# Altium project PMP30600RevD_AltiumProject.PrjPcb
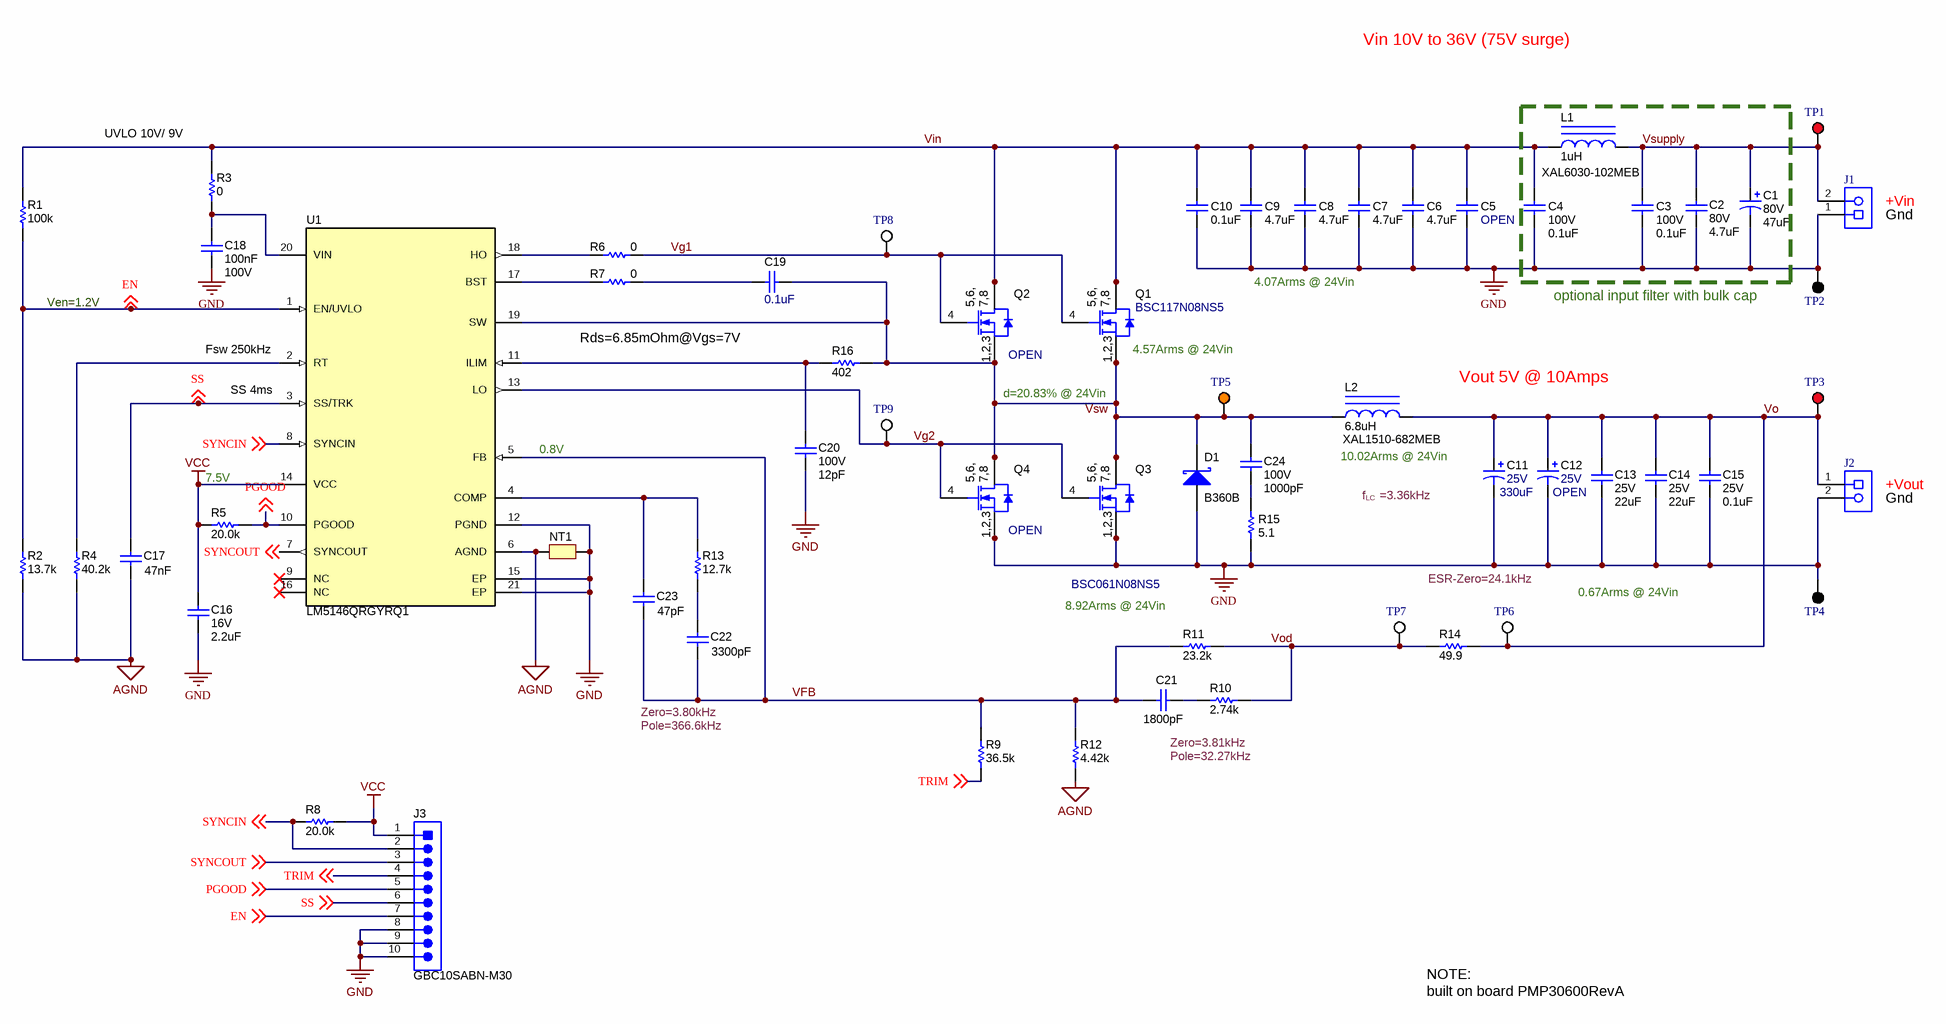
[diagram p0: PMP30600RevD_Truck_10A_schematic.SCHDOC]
TID: N/A; TechSupport: http://www.ti.com/support; SCH_Rev: D; PRJ_Title: Automotive Pre Regulator 10A (Truck); PRJ_Number: PMP30600-TL; PRJ_Engineer: Nobukazu Tsukiji; PRJ_Customer: Public Release; PCB_Rev: A; PCB_Layout: Who did the Layout?
1 sheet, 61 parts. Net scope: global (net labels, ports and power ports of the same name join across sheets).
Board file: PMP30600RevA_board.PcbDoc

## Sheet PMP30600RevD_Truck_10A_schematic.SCHDOC
size 431 x 279 mm; Date: Not shown in title block; ApprovedBy: Not shown in title block; CheckedBy: Not shown in title block; Author: Not shown in title block; CompanyName: Not shown in title block; Engineer: Not shown in title block; Organization: Not shown in title block; Address1: Not shown in title block; Address2: Not shown in title block; Address3: Not shown in title block; Address4: Not shown in title block; DocumentNumber: 1; Revision: Use project parameter SCH_Rev; SheetNumber: 1; SheetTotal: 1; PageSetup: Record=PageOptions¦CenterHorizontal=True¦CenterVertical=True¦PrintScale=0.70¦XCorrection=1.00¦YCorrection=1.00¦PrintKind=0¦BorderSize=5000000¦LeftOffset=0¦BottomOffset=0¦Orientation=2¦PaperLength=1000¦PaperWidth=1000¦Scale=100¦PaperSource=15¦PrintQuality=600¦MediaType=1¦DitherType=10¦PaperKind=A4¦PrintScaleMode=1

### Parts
C1  VDC_V: 80V  ValueDisplayed: 47uF  [SM_RADIAL_6.3AMM]  (hidden comment: EEHZC1K470P)
C2  VDC_V: 80V  ValueDisplayed: 4.7uF  [1210_270]  (hidden comment: GRM32ER71K475KE14L)
C3  VDC_V: 100V  ValueDisplayed: 0.1uF  [0603]  (hidden comment: GRM188R72A104KA35J)
C4  VDC_V: 100V  ValueDisplayed: 0.1uF  [0603]  (hidden comment: GRM188R72A104KA35J)
C5  ValueDisplayed: OPEN  [1210_270]  (hidden comment: Capacitor)
C6  ValueDisplayed: 4.7uF  [1210_270]  (hidden comment: GRM32ER71K475KE14L)
C7  ValueDisplayed: 4.7uF  [1210_270]  (hidden comment: GRM32ER71K475KE14L)
C8  ValueDisplayed: 4.7uF  [1210_270]  (hidden comment: GRM32ER71K475KE14L)
C9  ValueDisplayed: 4.7uF  [1210_270]  (hidden comment: GRM32ER71K475KE14L)
C10  ValueDisplayed: 0.1uF  [0603]  (hidden comment: GRM188R72A104KA35J)
C11  VDC_V: 25V  ValueDisplayed: 330uF  [SM_RADIAL_10BMM]  (hidden comment: EEHZC1E331P)
C12  VDC_V: 25V  ValueDisplayed: OPEN  [SM_RADIAL_10BMM]  (hidden comment: EEHZC1E331P)
C13  VDC_V: 25V  ValueDisplayed: 22uF  [1210_270]  (hidden comment: GRM32ER71E226KE15L)
C14  VDC_V: 25V  ValueDisplayed: 22uF  [1210_270]  (hidden comment: GRM32ER71E226KE15L)
C15  VDC_V: 25V  ValueDisplayed: 0.1uF  [0603]  (hidden comment: GRM188R71E104KA01D)
C16  VDC_V: 16V  ValueDisplayed: 2.2uF  [0805_HV]  (hidden comment: GRM21BR71C225KA12L)
C17  ValueDisplayed: 47nF  [0603]  (hidden comment: GRM188R71E473KA01D)
C18  Cap_F: 100nF  VDC_V: 100V  [0603]  (hidden comment: GRM188R72A104KA35D)
C19  ValueDisplayed: 0.1uF  [0603]  (hidden comment: Capacitor)
C20  VDC_V: 100V  ValueDisplayed: 12pF  [0603]  (hidden comment: GRM1885C2A120JA01D)
C21  ValueDisplayed: 1800pF  [0603]  (hidden comment: GRM1885C1H182JA01D)
C22  ValueDisplayed: 3300pF  [0603]  (hidden comment: GRM1885C1H332JA01D)
C23  ValueDisplayed: 47pF  [0603]  (hidden comment: GRM1885C1H470JA01D)
C24  VDC_V: 100V  ValueDisplayed: 1000pF  [0805_HV]  (hidden comment: C0805C102K1RACTU)
D1  PartNumberDisplayed: B360B  [SMB]  (hidden comment: B360B-13-F)
J1  691214110002  [Wurth_691214110002]  (value not drawn)
J2  691236510002  [Wurth_691236510002]  (value not drawn)
J3  GBC10SABN-M30  [Sullins_GBC10SABN-M30]
L1  XAL6030-102MEB  ValueDisplayed: 1uH  [XAL6030]
L2  ValueDisplayed: 6.8uH  [XAL1510]  (hidden comment: XAL1510-682MEB)
NT1  Net-Tie  [Net-Tie_10milWide_30milLong]  (value not drawn)  (net tie, no BOM)
Q1  BSC117N08NS5  [PG-TDSON-8]
Q2  OPEN  [PG-TDSON-8]
Q3  BSC061N08NS5  [PG-TDSON-8]
Q4  OPEN  [PG-TDSON-8]
R1  ValueDisplayed: 100k  [0603]  (hidden comment: CRCW0603100KFKEA)
R2  ValueDisplayed: 13.7k  [0603]  (hidden comment: CRCW060313K7FKEA)
R3  ValueDisplayed: 0  [0603]  (hidden comment: RMCF0603ZT0R00)
R4  ValueDisplayed: 40.2k  [0603]  (hidden comment: CRCW060340K2FKEA)
R5  ValueDisplayed: 20.0k  [0603]  (hidden comment: CRCW060320K0FKEA)
R6  ValueDisplayed: 0  [0603]  (hidden comment: RMCF0603ZT0R00)
R7  ValueDisplayed: 0  [0603]  (hidden comment: RMCF0603ZT0R00)
R8  ValueDisplayed: 20.0k  [0603]  (hidden comment: CRCW060320K0FKEA)
R9  ValueDisplayed: 36.5k  [0603]  (hidden comment: RC0603FR-0736K5L)
R10  ValueDisplayed: 2.74k  [0603]  (hidden comment: CRCW06032K74FKEA)
R11  ValueDisplayed: 23.2k  [0603]  (hidden comment: CRCW060323K2FKEA)
R12  ValueDisplayed: 4.42k  [0603]  (hidden comment: CRCW06034K42FKEA)
R13  ValueDisplayed: 12.7k  [0603]  (hidden comment: CRCW060312K7FKEA)
R14  ValueDisplayed: 49.9  [0603]  (hidden comment: CRCW060349R9FKEA)
R15  ValueDisplayed: 5.1  [1210]  (hidden comment: RC1210JR-075R1L)
R16  ValueDisplayed: 402  [0603]  (hidden comment: CRCW0603402RFKEA)
TP1  5000  [Keystone5000]  (value not drawn)
TP2  5001  [Keystone5001]  (value not drawn)
TP3  5000  [Keystone5000]  (value not drawn)
TP4  5001  [Keystone5001]  (value not drawn)
TP5  5003  [Keystone5003]  (value not drawn)
TP6  5002  [Keystone5002]  (value not drawn)
TP7  5002  [Keystone5002]  (value not drawn)
TP8  5002  [Keystone5002]  (value not drawn)
TP9  5002  [Keystone5002]  (value not drawn)
U1  LM5146QRGYRQ1  [RGY0020B]

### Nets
AGND: C17.2 NT1.1 R2.1 R4.1 R12.1 U1.6(AGND)
GND: C1.2(-) C2.2 C3.2 C4.2 C5.2 C6.2 C7.2 C8.2 C9.2 C10.2 C11.2(-) C12.2(-) C13.2 C14.2 C15.2 C16.2 C18.2 C20.2 D1.2(A) J1.1 J2.2 J3.8 J3.9 J3.10 NT1.2 Q3.1(S) Q3.2(S) Q3.3(S) Q4.1(S) Q4.2(S) Q4.3(S) R15.1 TP2.1 TP4.1 U1.12(PGND) U1.15(EP) U1.21(EP)
VCC: C16.1 J3.1 R5.1 R8.2 U1.14(VCC)
EN: J3.7 R1.1 R2.2 U1.1(EN/UVLO) ; off-sheet EN
PGOOD: J3.5 R5.2 U1.10(PGOOD) ; off-sheet PGOOD
SS: C17.1 J3.6 U1.3(SS/TRK) ; off-sheet SS
SYNCIN: J3.2 R8.1 U1.8(SYNCIN) ; off-sheet SYNCIN
SYNCOUT: J3.3 U1.7(SYNCOUT) ; off-sheet SYNCOUT
TRIM: J3.4 R9.1 ; off-sheet TRIM
VFB: C21.2 C22.1 C23.1 R9.2 R11.1 R12.2 U1.5(FB)
Vg1: Q1.4(G) Q2.4(G) R6.2 TP8.1
Vg2: Q3.4(G) Q4.4(G) TP9.1 U1.13(LO)
Vin: C4.1 C5.1 C6.1 C7.1 C8.1 C9.1 C10.1 L1.1 Q1.5(D) Q1.6(D) Q1.7(D) Q1.8(D) Q1.9(D) Q2.5(D) Q2.6(D) Q2.7(D) Q2.8(D) Q2.9(D) R1.2 R3.2
Vo: C11.1(+) C12.1(+) C13.1 C14.1 C15.1 J2.1 L2.2 R14.2 TP3.1 TP6.1
Vod: R10.2 R11.2 R14.1 TP7.1
Vsupply: C1.1(+) C2.1 C3.1 J1.2 L1.2 TP1.1
NetC18_1: C18.1 R3.1 U1.20(VIN)
NetC19_1: C19.1 R7.2
NetC19_2: C19.2 C24.1 D1.1(K) L2.1 Q1.1(S) Q1.2(S) Q1.3(S) Q2.1(S) Q2.2(S) Q2.3(S) Q3.5(D) Q3.6(D) Q3.7(D) Q3.8(D) Q3.9(D) Q4.5(D) Q4.6(D) Q4.7(D) Q4.8(D) Q4.9(D) R16.2 TP5.1 U1.19(SW)
NetC20_1: C20.1 R16.1 U1.11(ILIM)
NetC21_1: C21.1 R10.1
NetC22_2: C22.2 R13.2
NetC23_2: C23.2 R13.1 U1.4(COMP)
NetC24_2: C24.2 R15.2
NetR4_2: R4.2 U1.2(RT)
NetR6_1: R6.1 U1.18(HO)
NetR7_1: R7.1 U1.17(BST)

Not connected (* = marked no-connect by the designer): U1 9(NC)* 16(NC)*

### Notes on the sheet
- Vin 10V to 36V (75V surge)
- (near R3) UVLO 10V/ 9V
- (near J1) +Vin
- (near J1) Gnd
- 4.07Arms @ 24Vin
- Ven=1.2V
- (near U1) Fsw 250kHz
- Rds=6.85mOhm@Vgs=7V
  ILIM=13A
- (near Q1) 4.57Arms @ 24Vin
- (near TP2) optional input filter with bulk cap
- (near U1) SS 4ms
- d=20.83% @ 24Vin
- Vout 5V @ 10Amps
- (near R5) 7.5V
- (near U1) 0.8V
- 10.02Arms @ 24Vin
- (near J2) +Vout
- LC
- f    =3.36kHz
- (near J2) Gnd
- (near R11) 8.92Arms @ 24Vin
- ESR-Zero=24.1kHz
- 0.67Arms @ 24Vin
- Zero=3.80kHz
- Pole=366.6kHz
- Zero=3.81kHz
- Pole=32.27kHz
- built on board PMP30600RevA
- NOTE:
- Labels drawn without touching a wire or pin: Vsw

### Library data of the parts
C1 = CMP-0012607-3: CAP, Polymer Hybrid, 47 uF, 35 V, +/- 20%, 60 ohm, 6.3x5.8 SMD; Manufacturer: Panasonic; PartNumber: EEHZC1V470P; TaMin_C: -55°C; ESR_ohm: 60; Polarized: Y; SizeAreaWB_mm2: 79.98; Value1: 60 ohm; Value: 47uF; TaMax_C: 125°C; SizeZ_mm: 6; SizeX_mm: 7.3; SizeY_mm: 6.6; Value2: 35V; SizeArea_mm2: 48.18; CompType: Capacitor; Cap_F: 47µF; IRMS_A: 900mA; AEC Category: Q200
C2 = CMP-0009230-2: CAP, CERM, 4.7 uF, 80 V, +/- 10%, X7R, 1210; Manufacturer: MuRata; TaMin_C: -55°C; Polarized: N; SizeAreaWB_mm2: 14.7; Value1: Unknown; U/M: EA; Value: 4.7uF; TaMax_C: 125°C; SizeZ_mm: 2.7; SizeX_mm: 3.2; SizeY_mm: 2.5; Cap_Case: 1210; SizeArea_mm2: 8; Cap_F: 4.7µF; AEC Category: Q200
C3 C4 = CMP-0007470-5: CAP, CERM, 0.1 uF, 100 V, +/- 10%, X7R, 0603; Manufacturer: MuRata; TaMin_C: -55°C; Polarized: N; SizeAreaWB_mm2: 4.68; Value1: Unknown; U/M: EA; Value: 0.1uF; TaMax_C: 125°C; SizeZ_mm: 1; SizeX_mm: 1.6; SizeY_mm: 0.8; SizeArea_mm2: 1.28; Cap_F: 100nF; AEC Category: Q200
C5 = CMP-0009226-3: CAP, CERM, 10 uF, 50 V, +/- 10%, X7R, 1210; PartNumber: GRM32ER71H106KA12L; Manufacturer: MuRata; Polarized: N; Value: 10uF; U/M: EA; Cap_F: 10µF; Value1: Unknown; VDC_V: 50V; TaMin_C: -55°C; TaMax_C: 125°C; Cap_Case: 1210; SizeArea_mm2: 8; SizeAreaWB_mm2: 14.7; SizeX_mm: 3.2; SizeY_mm: 2.5; SizeZ_mm: 2.7; AEC Category: Q200
C6-C9 = CMP-0009230-2: CAP, CERM, 4.7 uF, 80 V, +/- 10%, X7R, 1210; Manufacturer: MuRata; TaMin_C: -55°C; Polarized: N; SizeAreaWB_mm2: 14.7; Value1: Unknown; U/M: EA; Value: 4.7uF; TaMax_C: 125°C; SizeZ_mm: 2.7; SizeX_mm: 3.2; SizeY_mm: 2.5; Cap_Case: 1210; Value2: 80V; SizeArea_mm2: 8; Cap_F: 4.7µF; AEC Category: Q200
C10 = CMP-0007470-5: CAP, CERM, 0.1 uF, 100 V, +/- 10%, X7R, 0603; Manufacturer: MuRata; TaMin_C: -55°C; Polarized: N; SizeAreaWB_mm2: 4.68; Value1: Unknown; U/M: EA; Value: 0.1uF; TaMax_C: 125°C; SizeZ_mm: 1; SizeX_mm: 1.6; SizeY_mm: 0.8; Value2: 100V; SizeArea_mm2: 1.28; Cap_F: 100nF; AEC Category: Q200
C11 C12 = CMP-0012593-1: CAP, Polymer Hybrid, 330 uF, 25 V, +/- 20%, 20 ohm, 10x10 SMD; Manufacturer: Panasonic; TaMin_C: -55°C; ESR_ohm: 20; Polarized: Y; SizeAreaWB_mm2: 159.9; Value1: 20 ohm; U/M: EA; Value: 330uF; TaMax_C: 125°C; SizeZ_mm: 10.2; SizeX_mm: 11; SizeY_mm: 10.3; SizeArea_mm2: 113.3; CompType: Capacitor; Cap_F: 330µF; IRMS_A: 2A; AEC Category: Q200
C13 C14 = CMP-0009224-2: CAP, CERM, 22 uF, 25 V, +/- 10%, X7R, 1210; Manufacturer: MuRata; TaMin_C: -55°C; Polarized: N; SizeAreaWB_mm2: 14.7; Value1: Unknown; U/M: EA; Value: 22uF; TaMax_C: 125°C; SizeZ_mm: 2.7; SizeX_mm: 3.2; SizeY_mm: 2.5; Cap_Case: 1210; SizeArea_mm2: 8; Cap_F: 22µF; AEC Category: Q200
C15 = CMP-0007404-4: CAP, CERM, 0.1 uF, 25 V, +/- 10%, X7R, 0603; Manufacturer: MuRata; TaMin_C: -55°C; Polarized: N; SizeAreaWB_mm2: 4.68; Value1: Unknown; U/M: EA; Value: 0.1uF; TaMax_C: 125°C; SizeZ_mm: 1; SizeX_mm: 1.6; SizeY_mm: 0.8; SizeArea_mm2: 1.28; Cap_F: 100nF; AEC Category: Q200
C16 = CMP-0008329-2: CAP, CERM, 2.2 uF, 16 V, +/- 10%, X7R, 0805; Manufacturer: MuRata; TaMin_C: -55°C; ESR_ohm: 4m; Polarized: N; SizeAreaWB_mm2: 6.75; Value1: 0.004 ohm; U/M: EA; Value: 2.2uF; TaMax_C: 125°C; SizeZ_mm: 1.45; SizeX_mm: 2; SizeY_mm: 1.25; Cap_Case: 0805; SizeArea_mm2: 2.5; Cap_F: 2.2µF; AEC Category: Q200
C17 = CMP-0007423-4: CAP, CERM, 0.047 uF, 25 V, +/- 10%, X7R, 0603; Manufacturer: MuRata; TaMin_C: -55°C; Polarized: N; SizeAreaWB_mm2: 4.68; Value1: Unknown; U/M: EA; TaMax_C: 125°C; SizeZ_mm: 1; SizeX_mm: 1.6; SizeY_mm: 0.8; Value2: 25V; SizeArea_mm2: 1.28; AEC Category: Q200
C18 = CMP-0007469-4: CAP, CERM, 0.1 uF, 100 V, +/- 10%, X7R, 0603; Manufacturer: MuRata; TaMin_C: -55°C; Polarized: N; SizeAreaWB_mm2: 4.68; Value1: Unknown; U/M: EA; Value: 0.1uF; TaMax_C: 125°C; SizeZ_mm: 1; SizeX_mm: 1.6; SizeY_mm: 0.8; SizeArea_mm2: 1.28; AEC Category: Q200
C19 = CMP-0007434-4: CAP, CERM, 0.1 uF, 50 V, +/- 10%, X7R, 0603; PartNumber: GRM188R71H104KA93D; Manufacturer: MuRata; Polarized: N; Value: 0.1uF; U/M: EA; Cap_F: 100nF; Value1: Unknown; VDC_V: 50V; TaMin_C: -55°C; TaMax_C: 125°C; SizeArea_mm2: 1.28; SizeAreaWB_mm2: 4.68; SizeX_mm: 1.6; SizeY_mm: 0.8; SizeZ_mm: 1; AEC Category: Q200
C20 = CMP-0007241-4: CAP, CERM, 12 pF, 100 V, +/- 5%, C0G/NP0, 0603; Manufacturer: MuRata; TaMin_C: -55°C; Polarized: N; SizeAreaWB_mm2: 4.68; Value1: Unknown; U/M: EA; Value: 12pF; TaMax_C: 125°C; SizeZ_mm: 1; SizeX_mm: 1.6; SizeY_mm: 0.8; SizeArea_mm2: 1.28; AEC Category: Q200
C21 = CMP-0007192-4: CAP, CERM, 1800 pF, 50 V, +/- 5%, C0G/NP0, 0603; Manufacturer: MuRata; TaMin_C: -55°C; Polarized: N; SizeAreaWB_mm2: 4.68; Value1: Unknown; U/M: EA; Value: 1800pF; TaMax_C: 125°C; SizeZ_mm: 1; SizeX_mm: 1.6; SizeY_mm: 0.8; Value2: 50V; SizeArea_mm2: 1.28; Cap_F: 1.8nF; AEC Category: Q200
C22 = CMP-0007210-4: CAP, CERM, 3300 pF, 50 V, +/- 5%, C0G/NP0, 0603; Manufacturer: MuRata; TaMin_C: -55°C; Polarized: N; SizeAreaWB_mm2: 4.68; Value1: Unknown; U/M: EA; Value: 3300pF; TaMax_C: 125°C; SizeZ_mm: 1; SizeX_mm: 1.6; SizeY_mm: 0.8; Value2: 50V; SizeArea_mm2: 1.28; Cap_F: 3.3nF; AEC Category: Q200
C23 = CMP-0007220-4: CAP, CERM, 47 pF, 50 V, +/- 5%, C0G/NP0, 0603; Manufacturer: MuRata; TaMin_C: -55°C; Polarized: N; SizeAreaWB_mm2: 4.68; Value1: Unknown; U/M: EA; Value: 47pF; TaMax_C: 125°C; SizeZ_mm: 1; SizeX_mm: 1.6; SizeY_mm: 0.8; Value2: 50V; SizeArea_mm2: 1.28; AEC Category: Q200
C24 = CMP-0007713-2: CAP, CERM, 1000 pF, 100 V, +/- 10%, X7R, 0805; Manufacturer: Kemet; TaMin_C: -55°C; ESR_ohm: 0.384; Polarized: N; SizeAreaWB_mm2: 6.75; Value1: 0.384 ohm; U/M: EA; Value: 1000pF; TaMax_C: 125°C; SizeZ_mm: 1.45; SizeX_mm: 2; SizeY_mm: 1.25; Cap_Case: 0805; SizeArea_mm2: 2.5; Cap_F: 1nF; IRMS_A: 214mA; AEC Category: Q200
D1 = CMP-0028420-1: Diode, Schottky, 60 V, 3 A, SMB; Manufacturer: Diodes Inc.; Io_A: 3A; Green_Lifecycle: Active; SizeAreaWB_mm2: 44.156; Vr_V: 60V; Green_REACh: Passed; TJmax_C: 125°C; U/M: EA; Value: 60V; SizeZ_mm: 2.6; SizeX_mm: 5.6; SizeY_mm: 3.81; Vf_V: 700mV; Value2: 0.7V; SizeArea_mm2: 21.336; AEC Category: Q101; RJC_CperW: 25
J1 = CMP-0054825-2: Terminal Block, 3.5mm, 2x1, Tin, TH; Manufacturer: Wurth Elektronik; Pitch_mm: 3.5; CT: TRUE; CNHeader: FALSE; Voltage_V: 300V; Gender: Female; Cert_UL: Y; Row_Count: 1; Current_A: 10A
J2 = CMP-0079044-1: Terminal Block, 5.08mm, 2x1, R/A, TH; Manufacturer: Wurth Elektronik; Pitch_mm: 5.08; Cert_VDE: Y; Gender: Female; Voltage_V: 300V; Current_A: 20A; Row_Count: 1
J3 = CMP-0054626-1: Header, 2.54mm, 10x1, Gold, SMT; Manufacturer: Sullins Connector Solutions; CNHeader: TRUE; Current_A: 3A; Shrouded: N; Gender: Male; Voltage_V: 600V; Row_Count: 1; Pitch_mm: 2.54; CT: FALSE; Cert_UL: Y
L1 = CMP-0061011-1: Inductor, Shielded, Composite, 1 uH, 21.5 A, 0.01 ohm, SMD; Manufacturer: Coilcraft; Isat: 23A @ 30% inductance drop; Irms: 21.5A @ 40C rise; Green_Lifecycle: Not Set; SizeAreaWB_mm2: 71.5616; DCR_ohm: 0.01; Green_REACh: Incomplete; Value: 1uH; Imax_A: 21.5A; SizeZ_mm: 3.1; SizeX_mm: 6.36; SizeY_mm: 6.56; SizeArea_mm2: 41.7216; Ind_H: 1µH; AEC Category: Q200
L2 = CMP-0060971-1: Inductor, Shielded, Composite, 6.8 uH, 26 A, 0.00417 ohm, SMD; Manufacturer: Coilcraft; Isat: 36A @ 30% inductance drop; Irms: 26A @ 40C rise; SizeAreaWB_mm2: 320.16; DCR_ohm: 4.17m; Value: 6.8uH; Imax_A: 26A; SizeZ_mm: 10; SizeX_mm: 16.4; SizeY_mm: 15.4; SizeArea_mm2: 252.56; Ind_H: 6.8µH; AEC Category: Q200
NT1 = CMP-0078142-1: Single point connection between nets.
Q1 = CMP-0000906-1: MOSFET, N-CH, 80 V, 49 A, PG-TDSON-8; PartNumber: BSC117N08NS5ATMA1; Alternate Manufacturer: None; Manufacturer: Infineon Technologies; SizeZ_mm: 1.12; ChType: N; Value2: 15 nC; VdsMax_V: 80V; SizeX_mm: 5.99; SizeY_mm: 4.9; Vgs_V: 20V; QgTyp_nC: 15; Value: 80V; SizeArea_mm2: 29.351; AEC Category: Q101; IdsMax_A: 49A; SizeAreaWB_mm2: 55.131; U/M: EA
Q2-Q4 = CMP-0000904-1: MOSFET, N-CH, 80 V, 82 A, PG-TDSON-8; PartNumber: BSC061N08NS5ATMA1; Alternate Manufacturer: None; Manufacturer: Infineon Technologies; SizeZ_mm: 1.12; ChType: N; Value2: 27 nC; VdsMax_V: 80V; SizeX_mm: 5.99; SizeY_mm: 4.9; Vgs_V: 20V; QgTyp_nC: 27; Value: 80V; SizeArea_mm2: 29.351; AEC Category: Q101; IdsMax_A: 82A; SizeAreaWB_mm2: 55.131; U/M: EA
R1 = CMP-0021990-1: RES, 100 k, 1%, 0.1 W, 0603; Manufacturer: Vishay-Dale; Power_W: 100mW; TempCo: 100 ppm/C; U/M: EA; Value: 100k; EIA_Code: E96; SizeX_mm: 1.6; SizeY_mm: 0.8; SizeZ_mm: 1; Value2: 0.1W; SizeArea_mm2: 1.28; VDC_V: 75V; AEC Category: Q200
R2 = CMP-0022044-3: RES, 13.7 k, 1%, 0.1 W, 0603; Manufacturer: Vishay-Dale; Power_W: 100mW; TempCo: 100 ppm/C; Value_Code: 13k7; U/M: EA; Value: 13.7k; EIA_Code: E96; SizeX_mm: 1.6; SizeY_mm: 0.8; SizeZ_mm: 1; Value2: 0.1W; SizeArea_mm2: 1.28; VDC_V: 75V; AEC Category: Q200
R3 R6 R7 = CMP-0023343-1: RES, 0, 1%, 0.1 W, AEC-Q200 Grade 0, 0603; Manufacturer: Stackpole Electronics Inc; Power_W: 100mW; TempCo: ppm/C; U/M: EA; Value: 0; SizeX_mm: 1.6; SizeY_mm: 0.8; SizeZ_mm: 1; Value2: 0.1W; SizeArea_mm2: 1.28; AEC Qualified: Y; AEC Category: Q200
R4 = CMP-0022410-4: RES, 40.2 k, 1%, 0.1 W, AEC-Q200 Grade 0, 0603; Manufacturer: Vishay-Dale; Power_W: 100mW; TempCo: 100 ppm/C; Value_Code: 40k2; Value: 40.2k; EIA_Code: E96; SizeX_mm: 1.6; SizeY_mm: 0.8; SizeZ_mm: 1; Value2: 0.1W; SizeArea_mm2: 1.28; AEC Qualified: Y; VDC_V: 75V; AEC Category: Q200; AEC Grade: 0
R5 R8 = CMP-0022204-1: RES, 20.0 k, 1%, 0.1 W, 0603; Manufacturer: Vishay-Dale; Power_W: 100mW; TempCo: 100 ppm/C; Value_Code: 20k0; U/M: EA; Value: 20.0k; EIA_Code: E96; Res_ohm: 20k; SizeX_mm: 1.6; SizeY_mm: 0.8; SizeZ_mm: 1; Value2: 0.1W; SizeArea_mm2: 1.28; VDC_V: 75V; AEC Category: Q200
R9 = CMP-0023056-1: RES, 36.5 k, 1%, 0.1 W, 0603; Manufacturer: Yageo America; Power_W: 100mW; TempCo: 200 ppm/C; Value_Code: 36k5; U/M: EA; Value: 36.5k; EIA_Code: E96; SizeX_mm: 1.6; SizeY_mm: 0.8; SizeZ_mm: 1; Value2: 0.1W; SizeArea_mm2: 1.28; VDC_V: 150V; AEC Category: Q200
R10 = CMP-0022281-4: RES, 2.74 k, 1%, 0.1 W, AEC-Q200 Grade 0, 0603; Manufacturer: Vishay-Dale; Power_W: 100mW; TempCo: 100 ppm/C; Value_Code: 2k74; Value: 2.74k; EIA_Code: E96; SizeX_mm: 1.6; SizeY_mm: 0.8; SizeZ_mm: 1; Value2: 0.1W; SizeArea_mm2: 1.28; AEC Qualified: Y; VDC_V: 75V; AEC Category: Q200; AEC Grade: 0
R11 = CMP-0022228-3: RES, 23.2 k, 1%, 0.1 W, 0603; Manufacturer: Vishay-Dale; Power_W: 100mW; TempCo: 100 ppm/C; Value_Code: 23k2; U/M: EA; Value: 23.2k; EIA_Code: E96; SizeX_mm: 1.6; SizeY_mm: 0.8; SizeZ_mm: 1; Value2: 0.1W; SizeArea_mm2: 1.28; VDC_V: 75V; AEC Category: Q200
R12 = CMP-0022453-3: RES, 4.42 k, 1%, 0.1 W, 0603; Manufacturer: Vishay-Dale; Power_W: 100mW; TempCo: 100 ppm/C; Value_Code: 4k42; U/M: EA; Value: 4.42k; EIA_Code: E96; SizeX_mm: 1.6; SizeY_mm: 0.8; SizeZ_mm: 1; Value2: 0.1W; SizeArea_mm2: 1.28; VDC_V: 75V; AEC Category: Q200
R13 = CMP-0022032-4: RES, 12.7 k, 1%, 0.1 W, AEC-Q200 Grade 0, 0603; Manufacturer: Vishay-Dale; Power_W: 100mW; TempCo: 100 ppm/C; Value_Code: 12k7; Value: 12.7k; EIA_Code: E96; SizeX_mm: 1.6; SizeY_mm: 0.8; SizeZ_mm: 1; Value2: 0.1W; SizeArea_mm2: 1.28; AEC Qualified: Y; VDC_V: 75V; AEC Category: Q200; AEC Grade: 0
R14 = CMP-0022448-3: RES, 49.9, 1%, 0.1 W, 0603; Manufacturer: Vishay-Dale; Power_W: 100mW; TempCo: 100 ppm/C; Value_Code: 49R9; U/M: EA; Value: 49.9; EIA_Code: E96; SizeX_mm: 1.6; SizeY_mm: 0.8; SizeZ_mm: 1; Value2: 0.1W; SizeArea_mm2: 1.28; VDC_V: 75V; AEC Category: Q200
R15 = CMP-0083578-1: RES, 5.1, 5%, 0.5 W, 1210; Manufacturer: Yageo; Power_W: 500mW; TempCo: 200 ppm/C; SizeAreaWB_mm2: 14.7; Value_Code: 5R10; Value: 5.1; EIA_Code: E24; SizeX_mm: 3.2; SizeY_mm: 2.5; SizeZ_mm: 1.35; Value2: 0.5W; SizeArea_mm2: 8; AEC Qualified: N; VDC_V: 200V; AEC Category: Q200
R16 = CMP-0022409-5: RES, 402, 1%, 0.1 W, AEC-Q200 Grade 0, 0603; Manufacturer: Vishay-Dale; Power_W: 100mW; TempCo: 100 ppm/C; Value_Code: 402R; Value: 402; EIA_Code: E96; SizeX_mm: 1.6; SizeY_mm: 0.8; SizeZ_mm: 1; Value2: 0.1W; SizeArea_mm2: 1.28; AEC Qualified: Y; VDC_V: 75V; AEC Category: Q200; AEC Grade: 0
TP1 TP3 = CMP-0055137-1: Test Point, Miniature, Red, TH; Manufacturer: Keystone; CNHeader: FALSE; ContactFinish: Silver; CT: TRUE; Green_Lifecycle: Active; Green_REACh: Passed
TP2 TP4 = CMP-0055138-1: Test Point, Miniature, Black, TH; Manufacturer: Keystone; CNHeader: FALSE; ContactFinish: Silver; CT: TRUE; Green_Lifecycle: Active; Green_REACh: Passed
TP5 = CMP-0055140-1: Test Point, Miniature, Orange, TH; Manufacturer: Keystone; CNHeader: FALSE; ContactFinish: Silver; CT: TRUE; Green_Lifecycle: Active; Green_REACh: Passed
TP6-TP9 = CMP-0055139-1: Test Point, Miniature, White, TH; Manufacturer: Keystone; CNHeader: FALSE; ContactFinish: Silver; CT: TRUE; Green_Lifecycle: Active; Green_REACh: Passed
U1 = CMP-0081848-1: 5.5-V to 100-V Synchronous Buck Controller With Wide Duty Cycle Range, RGY0020B (VQFN-20); Alternate PartNumber: LM5146QRGYTQ1; Alternate Manufacturer: Texas Instruments; SizeAreaWB_mm2: 24.75; SizeZ_mm: 1; SizeX_mm: 3.5; SizeY_mm: 4.5; SizeArea_mm2: 15.75; CompType: IC; AEC Qualified: Y; AEC Category: Q200

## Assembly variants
001: not fitted FID1 FID2 FID3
